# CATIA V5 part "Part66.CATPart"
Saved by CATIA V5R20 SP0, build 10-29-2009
Part number: IA 3075SF
Revision: ANY
Definition: UNKNOWN
Nomenclature: IA 3075SF
Source: Unknown
Bounding box of the stored display mesh (mm): x -1.5 to 1.5, y -2.85 to 4.9, z -1.5 to 1.5
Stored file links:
  C:\Users\Utente\Desktop\IO LAVORO\3D X SITO CF\CUMSA\3D files FA\FA 053000\Part66.CATPart

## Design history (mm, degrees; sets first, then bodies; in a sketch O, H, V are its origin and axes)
Body1 "Cortar-Extruir1" (main body)
  Solid1: solid without history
